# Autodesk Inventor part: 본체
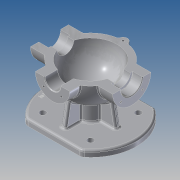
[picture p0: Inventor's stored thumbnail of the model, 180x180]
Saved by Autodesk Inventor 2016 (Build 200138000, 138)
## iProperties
Created: 2015-12
Part Number: 본체
Material: 알루미늄 6061
Document SubType Name: Modeling
Designer: mduedu
Density: 2.71 g/cm^3
Mass: 1035.31 g
Surface Area: 843.851 cm^2
Volume: 382.033 cm^3
Appearance: 알루미늄 - 평지
Author: mduedu
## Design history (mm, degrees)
sketch "스케치1"
  geometry: L1 (-53, 0)-(53, 0); A1 r 53 centre (0, 0) between (53, 0) and (-53, 0); 2 further points
  constraints: 2 coincident, 2 end point, 2 point on circle, 1 centre point, 1 horizontal, 1 midpoint
  dimensions: "d0" = 53 radius of A1
revolve "회전1" sketch "스케치1" stored, may be unused: angle "d2" = 90 deg
feature "쉘1" dims "d11" = 10
node "작업 평면1"
sketch "스케치2"
  geometry: C1 r 31 at (0, 0); 1 further point
  constraints: 1 centre point, 1 coincident
  dimensions: "d4" = 62 diameter of C1
extrude "돌출1" join sketch "스케치2" stored distance "d5" = 10; taper "d6" = 0 deg
node "작업 평면2"
sketch "스케치3"
  geometry: C1 r 28 at (0, 0); 1 further point
  constraints: 1 centre point, 1 coincident
  dimensions: "d8" = 56 diameter of C1
extrude "돌출2" join sketch "스케치3" stored distance "d9" = 10; taper "d10" = 0 deg
hole "구멍1" diameter "d14" = 35; stored, may be unused: countersink angle "d18" = 90 deg, drill point angle "d20" = 0 deg; dims "d12" = 10, "d13" = 10, "d15" = 6, "d16" = 4, "d17" = 2, "d19" = 16
hole "구멍2" diameter "d23" = 27; stored, may be unused: countersink angle "d27" = 90 deg, drill point angle "d29" = 0 deg; dims "d21" = 10, "d22" = 10, "d24" = 6, "d25" = 4, "d26" = 2, "d28" = 16
fillet "모깎기1" dims "d30" = 0.3
hole "구멍3" diameter "d33" = 26; stored, may be unused: countersink angle "d37" = 90 deg, drill point angle "d39" = 0 deg; dims "d31" = 10, "d32" = 10, "d34" = 6, "d35" = 4, "d36" = 2, "d38" = 16
chamfer "모따기1" distance "d40" = 1; stored, may be unused: second distance "d41" = 2, angle "d42" = 45 deg
sketch "스케치4"
  geometry: L1 (0, 0)-(0, -25); L2 (0, 0)-(-17.678, -17.678); A1 r 25 centre (0, 0) between (-17.678, -17.678) and (0, -25); 1 further point
  constraints: 4 end point, 2 point on circle, 1 centre point, 1 coincident, 1 vertical
  dimensions: "d43" = 50 diameter of A1; "d47" = 45 deg angle of L1 L2
hole "구멍4" sketch "스케치4" at (-17.678, -17.678) diameter "d49" = 3.242; stored, may be unused: countersink angle "d53" = 90 deg, drill point angle "d55" = 118 deg; dims "d50" = 11, "d51" = 4, "d52" = 2, "d54" = 13
sketch "스케치5"
  geometry: L1 (0, 0)-(0, -20); L2 (0, 0)-(-14.142, -14.142); A1 r 20 centre (0, 0) between (0, -20) and (-14.142, -14.142); 2 further points
  constraints: 4 end point, 2 coincident, 2 point on circle, 1 centre point, 1 vertical
  dimensions: "d59" = 40 diameter of A1; "d65" = 45 deg angle of L1 L2
hole "구멍5" sketch "스케치5" at (-14.142, -14.142) diameter "d67" = 3.242; stored, may be unused: countersink angle "d71" = 90 deg, drill point angle "d73" = 118 deg; dims "d68" = 8, "d69" = 4, "d70" = 2, "d72" = 10
node "작업 평면3"
sketch "스케치6"
  geometry: C1 r 75 at (0, 0); 1 further point
  constraints: 1 centre point, 1 coincident
  dimensions: "d78" = 150 diameter of C1
extrude "돌출3" join sketch "스케치6" distance "d80" = 10; taper "d81" = 0 deg
sketch "스케치7"
  geometry: C1 r 20 at (0, 0); 1 further point
  constraints: 1 centre point, 1 coincident
  dimensions: "d82" = 40 diameter of C1
extrude "돌출4" join sketch "스케치7" stored distance "d84" = 10; taper "d85" = 0 deg
sketch "스케치8"
  geometry: 2 further points
  constraints: 1 coincident
hole "구멍6" sketch "스케치8" at (0, 0) diameter "d86" = 20; stored, may be unused: countersink angle "d90" = 90 deg, drill point angle "d92" = 118 deg; dims "d87" = 7, "d88" = 40, "d89" = 5, "d91" = 10
fillet "모깎기2" dims "d93" = 0.3
sketch "스케치9"
  geometry: L1 (75, -75)-(-75, -75) reference; L2 (-45, -75)-(-38.245, -36.692); A1 r 53 centre (0, 0) between (42.988, 31) and (42.988, -31) reference; 1 further point
  constraints: 2 end point, 1 point on circle, 1 point on line
  dimensions: "d94" = 45 horizontal distance of L2.start point (0, 0); "d95" = 80 deg angle of L2 L1
feature "리브1" sketch "스케치9" dims "d96" = 1, "d97" = 8, "d98" = 0, "d99" = 0, "d100" = 1, "d101" = 1
sketch "스케치14"
  geometry: L1 (-45, 110)-(45, 110); L2 (45, 110)-(45, 60); L3 (45, 60)-(-45, 60); L4 (-45, 60)-(-45, 110); L5 (-45, 110)-(45, 60); L6 (45, 110)-(-45, 60); L7 (-75, 0)-(75, 0); L8 (-45, -110)-(45, -110); L9 (45, -110)-(45, -60); L10 (45, -60)-(-45, -60); L11 (-45, -60)-(-45, -110); L12 (-45, -110)-(45, -60); L13 (45, -110)-(-45, -60); A1 r 75 centre (0, 0) between (45, 60) and (-45, 60) reference; 4 further points
  constraints: 26 end point, 5 midpoint, 5 symmetric about line, 4 point on circle, 2 parallel, 2 perpendicular, 1 coincident, 1 horizontal
  dimensions: "d151" = 15 distance edge to line of A1 L3; "d152" = 50 distance of L3.end L1.start
extrude "돌출7" cut sketch "스케치14" stored distance "d153" = 0; taper "d154" = 0 deg
fillet "모깎기9" dims "d155" = 10
sketch "스케치10"
  geometry: L1 (0, 0)-(0, -55); L2 (0, 0)-(-38.891, -38.891); A1 r 55 centre (0, 0) between (0, -55) and (-38.891, -38.891); 2 further points
  constraints: 4 end point, 2 coincident, 2 point on circle, 1 centre point, 1 vertical
  dimensions: "d105" = 110 diameter of A1; "d107" = 45 deg angle of L1 L2
hole "구멍7" sketch "스케치10" at (-38.891, -38.891) diameter "d109" = 10; stored, may be unused: countersink angle "d113" = 90 deg, drill point angle "d115" = 118 deg; dims "d110" = 7, "d111" = 40, "d112" = 5, "d114" = 10
fillet "모깎기3" dims "d120" = 3
fillet "모깎기4" dims "d121" = 3, "d122" = 3
fillet "모깎기5" dims "d123" = 3
fillet "모깎기6" dims "d124" = 3
sketch "스케치11"
  geometry: 2 further points
  constraints: 1 vertical alignment, 1 other
  dimensions: "d157" = 63 distance of point (0, 63) point (0, 0)
feature "엠보싱1" sketch "스케치11" dims "d125" = 0.5, "d126" = 0
sketch "스케치12"
  geometry: L1 (0, 100)-(0, -100); L2 (0, 100)-(100, 100); L3 (100, 100)-(100, -100); L4 (100, -100)-(0, -100); 2 further points
  constraints: 8 end point, 3 perpendicular, 1 coincident, 1 midpoint, 1 vertical
  dimensions: "d127" = 200 distance of L2.end L3.end; "d129" = 100 distance between parallel lines of L1 L3
extrude "돌출5" cut sketch "스케치12" stored distance "d130" = 10; taper "d131" = 0 deg
sketch "스케치13"
  geometry: C1 r 7 at (0, 53); A1 r 53 centre (0, 0) between (42.113, 32.179) and (-42.113, 32.179) reference; 1 further point
  constraints: 1 centre point, 1 point on circle
  dimensions: "d132" = 14 diameter of C1
extrude "돌출6" join sketch "스케치13" distance "d134" = 15; taper "d135" = 0 deg; dims "d29" = 0
hole "구멍8" diameter "d139" = 3.242; stored, may be unused: countersink angle "d143" = 90 deg, drill point angle "d145" = 118 deg; dims "d140" = 8, "d141" = 4, "d142" = 2, "d144" = 10, "d148" = 10, "d149" = 10
fillet "모깎기7" dims "d146" = 3
fillet "모깎기8" dims "d147" = 3
node "솔리드1"
mirror "대칭1"
mirror "대칭2"
pattern_circular "원형 패턴1" dims angle "d57" = 360 deg
mirror "대칭3"
pattern_circular "원형 패턴2" dims angle "d75" = 360 deg
pattern_circular "원형 패턴3" dims angle "d103" = 360 deg
pattern_circular "원형 패턴4" dims angle "d118" = 360 deg
other parameters: "d3" = 67, "d7" = 62, "d77" = -85
